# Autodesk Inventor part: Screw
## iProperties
Shininess: 20.0
Length Units: 11269
Angle Units: 11279
Time Units: 11290
Mass Units: 11283
Length Display Precision: 3
Angle Display Precision: 2
Created: 2002-01
Part Number: Screw
Document SubType Name: Modeling
Designer: ***
Density: 0.0
Volumn: 0.0
Area: 0.0
PropertySet Name: Model Information
Control State: 0
Master: False
Checked Out: False
Author: ***
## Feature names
1. Revolution1
2. Extrusion2
3. Extrusion3
4. Chamfer1
